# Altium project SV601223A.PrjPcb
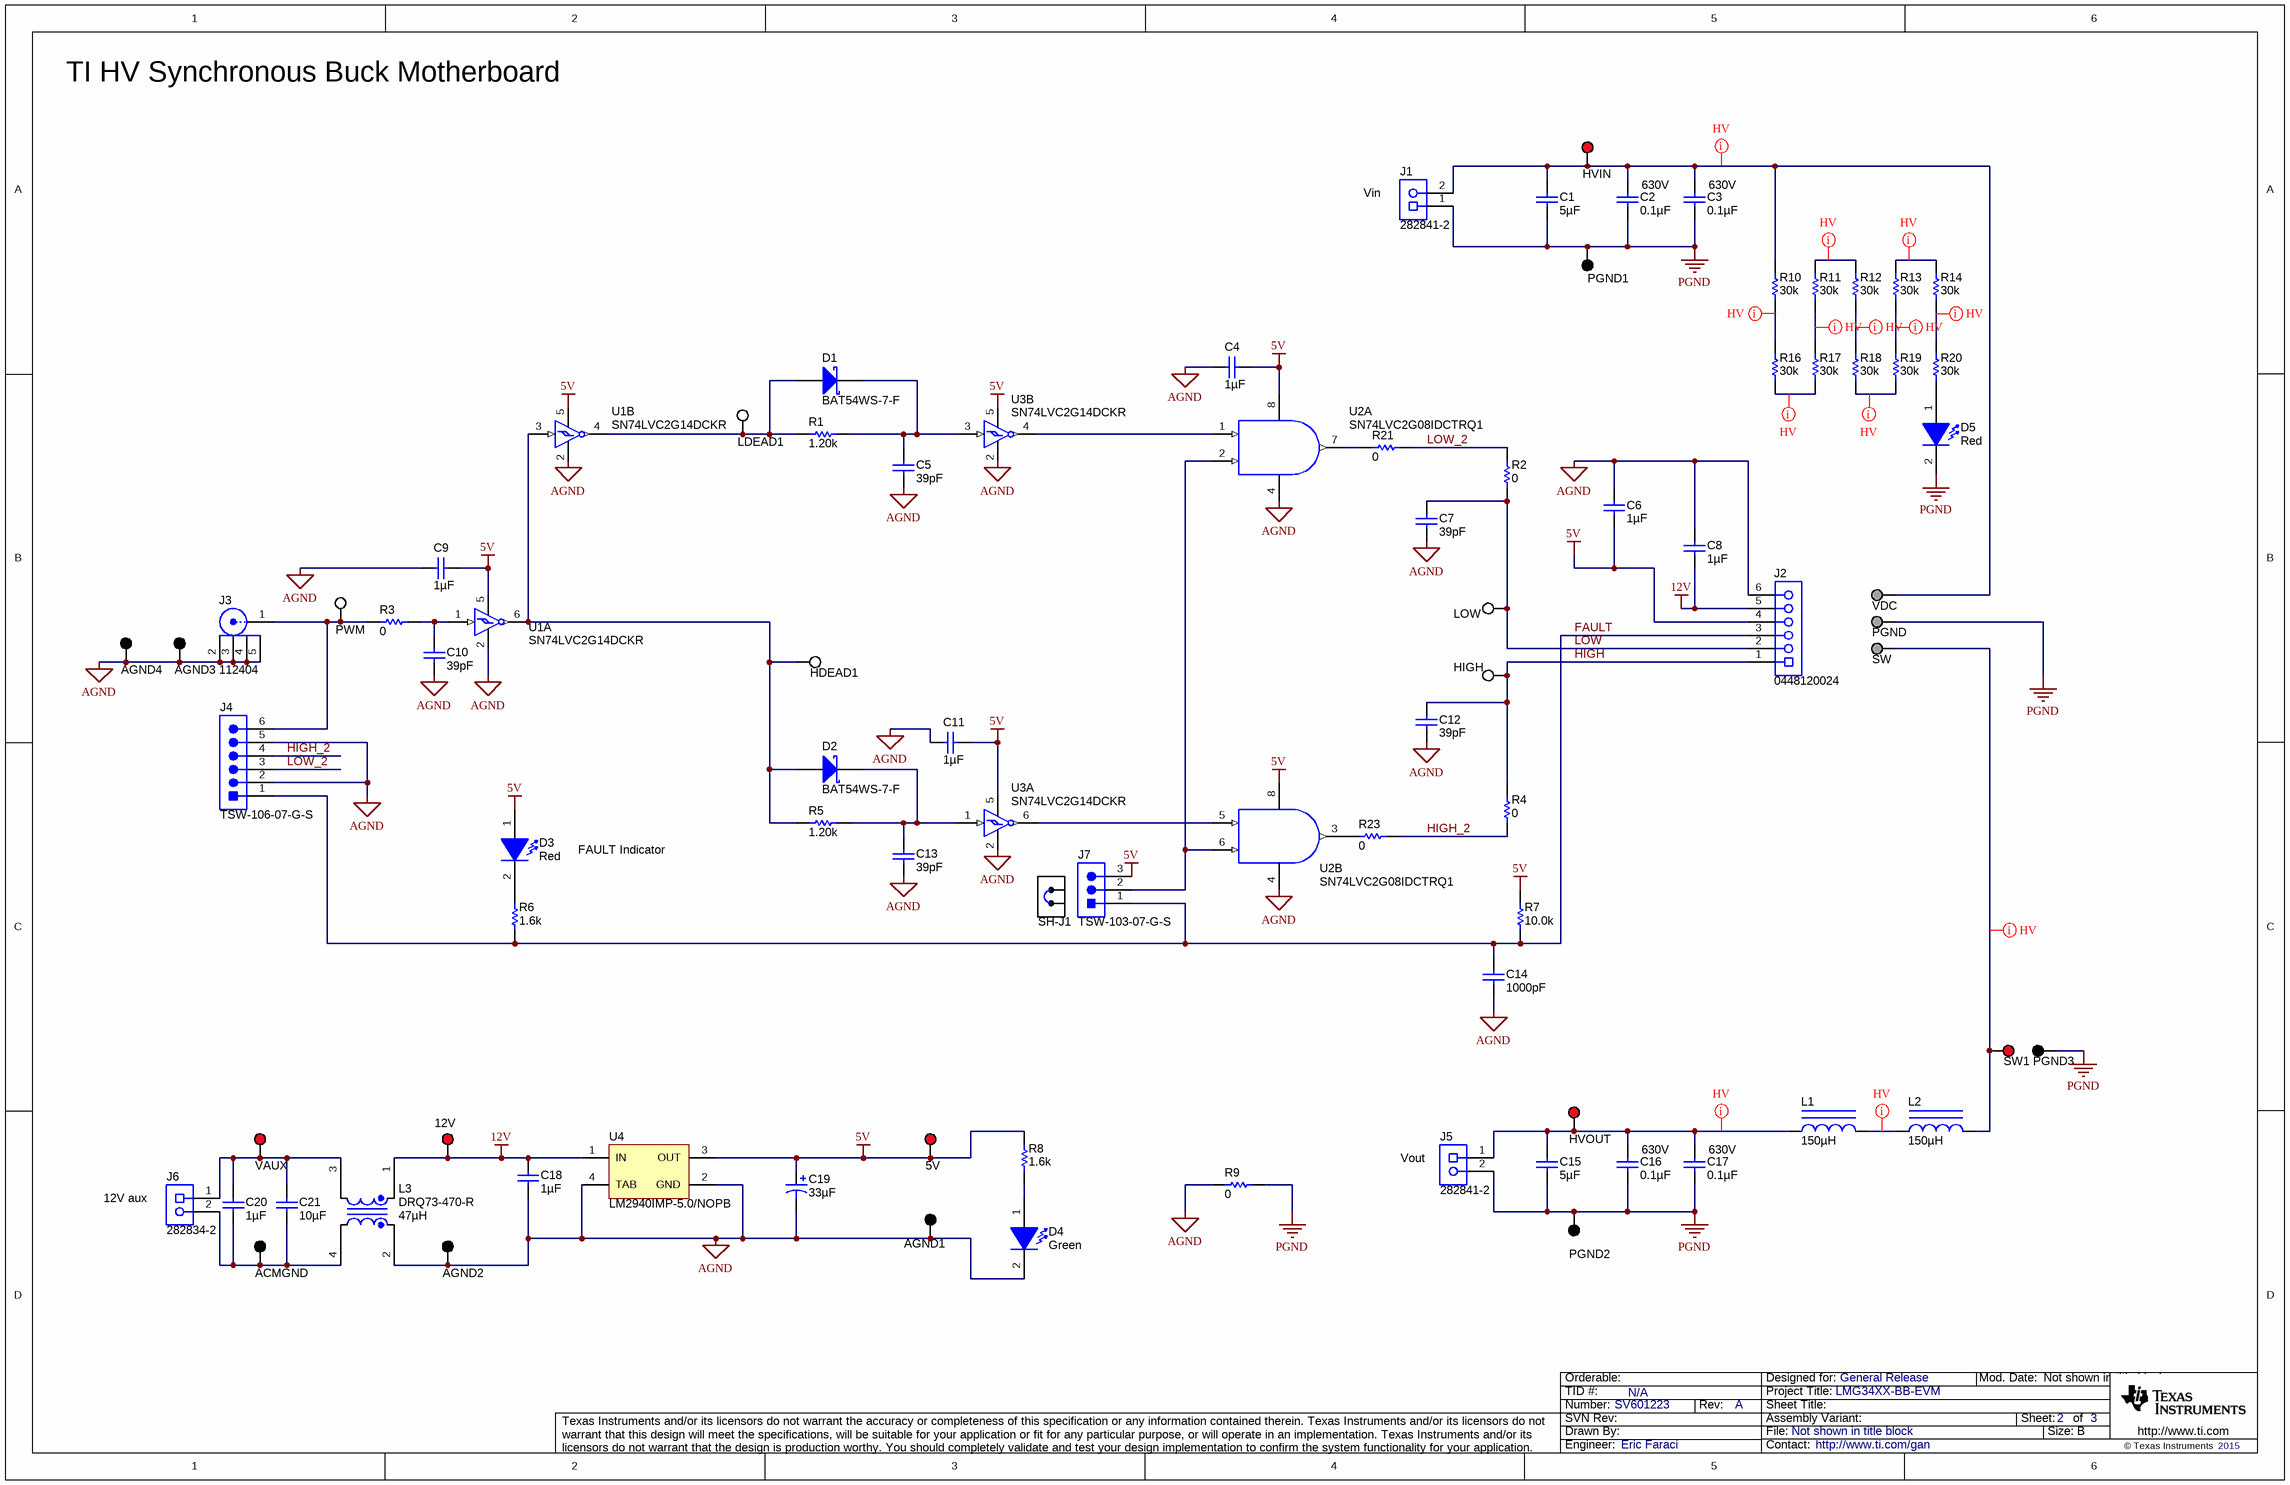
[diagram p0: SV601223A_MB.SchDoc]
TID: N/A; TechSupport: http://www.ti.com/gan; SCH_Rev: A; PRJ_Title: LMG34XX-BB-EVM; PRJ_Number: SV601223; PRJ_Engineer: Eric Faraci; PRJ_Customer: General Release; PCB_Rev: A; PCB_Layout: Eric Faraci; CopyrightYear: 2015
2 sheets, 112 parts. Net scope: global (net labels, ports and power ports of the same name join across sheets).
Board file: SV601223A.PcbDoc
Sheets:
  SV601223A_MB.SchDoc
  SV601223A_Hardware.SchDoc

## Sheet SV601223A_MB.SchDoc
size 431 x 279 mm; Date: Not shown in title block; ApprovedBy: Not shown in title block; CheckedBy: Not shown in title block; Author: Not shown in title block; CompanyName: Not shown in title block; Engineer: Not shown in title block; Organization: Not shown in title block; Address1: Not shown in title block; Address2: Not shown in title block; Address3: Not shown in title block; Address4: Not shown in title block; DocumentNumber: 1; Revision: Use project parameter SCH_Rev; SheetNumber: 2; SheetTotal: 3; PageSetup: Record=PageOptions¦CenterHorizontal=True¦CenterVertical=True¦PrintScale=1.00¦XCorrection=1.00¦YCorrection=1.00¦PrintKind=0¦BorderSize=5000000¦LeftOffset=0¦BottomOffset=0¦Orientation=2¦PaperLength=1000¦PaperWidth=1000¦Scale=100¦PaperSource=15¦PrintQuality=600¦MediaType=1¦DitherType=10¦PaperKind=Letter¦PrintScaleMode=1

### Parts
5V  5005  [Keystone5005]  (value not drawn)
12V  5005  [Keystone5005]  (value not drawn)
ACMGND  5006  [Keystone5006]  (value not drawn)
AGND1  5006  [Keystone5006]  (value not drawn)
AGND2  5006  [Keystone5006]  (value not drawn)
AGND3  5006  [Keystone5006]  (value not drawn)
AGND4  5006  [Keystone5006]  (value not drawn)
C1  ValueDisplayed: 5µF  [MKP1848Sx2_4200x1800x2700]  (hidden comment: MKP1848S55010JP2C)
C2  ValueDisplayed: 0.1µF  Value2: 630V  [1812]  (hidden comment: GRM43DR72J104KW01L)
C3  ValueDisplayed: 0.1µF  Value2: 630V  [1812]  (hidden comment: GRM43DR72J104KW01L)
C4  ValueDisplayed: 1µF  [0603]  (hidden comment: C1608X7R1E105K080AB)
C5  ValueDisplayed: 39pF  [0603]  (hidden comment: C1608C0G1H390J)
C6  ValueDisplayed: 1µF  [0603]  (hidden comment: C1608X7R1E105K080AB)
C7  ValueDisplayed: 39pF  [0603]  (hidden comment: C1608C0G1H390J)
C8  ValueDisplayed: 1µF  [0603]  (hidden comment: C1608X7R1E105K080AB)
C9  ValueDisplayed: 1µF  [0603]  (hidden comment: C1608X7R1E105K080AB)
C10  ValueDisplayed: 39pF  [0603]  (hidden comment: C1608C0G1H390J)
C11  ValueDisplayed: 1µF  [0603]  (hidden comment: C1608X7R1E105K080AB)
C12  ValueDisplayed: 39pF  [0603]  (hidden comment: C1608C0G1H390J)
C13  ValueDisplayed: 39pF  [0603]  (hidden comment: C1608C0G1H390J)
C14  ValueDisplayed: 1000pF  [0603]  (hidden comment: GRM1885C1E102JA01D)
C15  ValueDisplayed: 5µF  [MKP1848Sx2_4200x1800x2700]  (hidden comment: MKP1848S55010JP2C)
C16  ValueDisplayed: 0.1µF  Value2: 630V  [1812]  (hidden comment: GRM43DR72J104KW01L)
C17  ValueDisplayed: 0.1µF  Value2: 630V  [1812]  (hidden comment: GRM43DR72J104KW01L)
C18  ValueDisplayed: 1µF  [0603]  (hidden comment: GRM188R71E105KA12D)
C19  ValueDisplayed: 33µF  [3528-21]  (hidden comment: TPSB336K016R0350)
C20  ValueDisplayed: 1µF  [0603]  (hidden comment: GRM188R71E105KA12D)
C21  ValueDisplayed: 10µF  [0805_HV]  (hidden comment: GRM219R61E106KA12D)
D1  BAT54WS-7-F  [sod-323]
D2  BAT54WS-7-F  [sod-323]
D3  value Red  [LS L29K_Red]  (hidden comment: LS L29K-G1J2-1-Z)
D4  value Green  [LG L29K_GREEN]  (hidden comment: LG L29K-G2J1-24-Z)
D5  value Red  [LS L29K_Red]  (hidden comment: LS L29K-G1J2-1-Z)
HDEAD1  5012  [Keystone5012]  (value not drawn)
HIGH  5012  [Keystone5012]  (value not drawn)
HVIN  5005  [Keystone5005]  (value not drawn)
HVOUT  5005  [Keystone5005]  (value not drawn)
J1  282841-2  [TEC_282841-2]
J2  0448120024  [Molex_0448120024]
J3  112404  [Amphenol_112404]
J4  TSW-106-07-G-S  [TSW-106-07-G-S]
J5  282841-2  [TEC_282841-2]
J6  282834-2  [TEC_282834-2]
J7  TSW-103-07-G-S  [TSW-103-07-G-S]
L1  ValueDisplayed: 150µH  [2300HT-H]  (hidden comment: 2300HT-151-H-RC)
L2  ValueDisplayed: 150µH  [2300HT-H]  (hidden comment: 2300HT-151-H-RC)
L3  DRQ73-470-R  ValueDisplayed: 47µH  [DRQ73]
LDEAD1  5012  [Keystone5012]  (value not drawn)
LOW  5012  [Keystone5012]  (value not drawn)
PGND  Suggest using a net name here  [Mill-Max_0312-0-15-15-34-27-10-0]  (value not drawn)
PGND1  5006  [Keystone5006]  (value not drawn)
PGND2  5006  [Keystone5006]  (value not drawn)
PGND3  5006  [Keystone5006]  (value not drawn)
PWM  5012  [Keystone5012]  (value not drawn)
R1  ValueDisplayed: 1.20k  [0603]  (hidden comment: RC0603FR-071K2L)
R2  ValueDisplayed: 0  [0603]  (hidden comment: CRCW06030000Z0EA)
R3  ValueDisplayed: 0  [0603]  (hidden comment: CRCW06030000Z0EA)
R4  ValueDisplayed: 0  [0603]  (hidden comment: CRCW06030000Z0EA)
R5  ValueDisplayed: 1.20k  [0603]  (hidden comment: RC0603FR-071K2L)
R6  ValueDisplayed: 1.6k  [0603]  (hidden comment: CRCW06031K60JNEA)
R7  ValueDisplayed: 10.0k  [0603]  (hidden comment: ERJ-3EKF1002V)
R8  ValueDisplayed: 1.6k  [0603]  (hidden comment: CRCW06031K60JNEA)
R9  ValueDisplayed: 0  [0603]  (hidden comment: CRCW06030000Z0EA)
R10  ValueDisplayed: 30k  [1206]  (hidden comment: CRCW120630K0JNEA)
R11  ValueDisplayed: 30k  [1206]  (hidden comment: CRCW120630K0JNEA)
R12  ValueDisplayed: 30k  [1206]  (hidden comment: CRCW120630K0JNEA)
R13  ValueDisplayed: 30k  [1206]  (hidden comment: CRCW120630K0JNEA)
R14  ValueDisplayed: 30k  [1206]  (hidden comment: CRCW120630K0JNEA)
R16  ValueDisplayed: 30k  [1206]  (hidden comment: CRCW120630K0JNEA)
R17  ValueDisplayed: 30k  [1206]  (hidden comment: CRCW120630K0JNEA)
R18  ValueDisplayed: 30k  [1206]  (hidden comment: CRCW120630K0JNEA)
R19  ValueDisplayed: 30k  [1206]  (hidden comment: CRCW120630K0JNEA)
R20  ValueDisplayed: 30k  [1206]  (hidden comment: CRCW120630K0JNEA)
R21  ValueDisplayed: 0  [0603]  (hidden comment: CRCW06030000Z0EA)
R23  ValueDisplayed: 0  [0603]  (hidden comment: CRCW06030000Z0EA)
SH-J1  969102-0000-DA  [SNT-100-BK-G]  (value not drawn)
SW  Suggest using a net name here  [Mill-Max_0312-0-15-15-34-27-10-0]  (value not drawn)
SW1  5005  [Keystone5005]  (value not drawn)
U1  SN74LVC2G14DCKR  [DCK0006A_N]  (parts A,B of 2)
U2  SN74LVC2G08IDCTRQ1  [DCT0008A_N]  (parts A,B of 2)
U3  SN74LVC2G14DCKR  [DCK0006A_N]  (parts A,B of 2)
U4  LM2940IMP-5.0/NOPB  [MP04A_N]
VAUX  5005  [Keystone5005]  (value not drawn)
VDC  Suggest using a net name here  [Mill-Max_0312-0-15-15-34-27-10-0]  (value not drawn)

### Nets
5V: 5V.1 C4.2 C6.1 C9.2 C11.2 C19.1(+) D3.1(A) J2.4 J7.3 R7.2 R8.2 U1.5(VCC) U2.8(VCC) U3.5(VCC) U4.3(OUT)
12V: 12V.1 C8.1 C18.2 J2.5 L3.1 U4.1(IN)
AGND: AGND1.1 AGND2.1 AGND3.1 AGND4.1 C4.1 C5.2 C6.2 C7.2 C8.2 C9.1 C10.2 C11.1 C12.2 C13.2 C14.2 C18.1 C19.2(-) D4.2(K) J2.6 J3.2 J3.3 J3.4 J3.5 J4.2 J4.5 L3.2 R9.1 U1.2(GND) U2.4(GND) U3.2(GND) U4.2(GND) U4.4(TAB)
PGND: C1.2 C2.2 C3.2 C15.2 C16.2 C17.2 D5.2(K) J1.1 J5.2 PGND.1 PGND1.1 PGND2.1 PGND3.1 R9.2
FAULT: C14.1 J2.3 J4.1 J7.1 R6.1 R7.1
HIGH: C12.1 HIGH.1 J2.1 R4.2
HIGH_2: J4.4 R4.1 R23.1
LOW: C7.1 J2.2 LOW.1 R2.1
LOW_2: J4.3 R2.2 R21.1
NetACMGND_1: ACMGND.1 C20.1 C21.2 J6.2 L3.4
NetC1_1: C1.1 C2.1 C3.1 HVIN.1 J1.2 R10.2 VDC.1
NetC5_1: C5.1 D1.1(K) R1.2 U3.3(2A)
NetC10_1: C10.1 R3.1 U1.1(1A)
NetC13_1: C13.1 D2.1(K) R5.2 U3.1(1A)
NetC15_1: C15.1 C16.1 C17.1 HVOUT.1 J5.1 L1.1
NetC20_2: C20.2 C21.1 J6.1 L3.3 VAUX.1
NetD1_2: D1.2(A) LDEAD1.1 R1.1 U1.4(2Y)
NetD2_2: D2.2(A) HDEAD1.1 R5.1 U1.3(2A) U1.6(1Y)
NetD3_2: D3.2(K) R6.2
NetD4_1: D4.1(A) R8.1
NetD5_1: D5.1(A) R20.1
NetJ3_1: J3.1 J4.6 PWM.1 R3.2
NetJ7_2: J7.2 U2.2(1B) U2.6(2B)
NetL1_2: L1.2 L2.1
NetL2_2: L2.2 SW.1 SW1.1
NetR10_1: R10.1 R16.2
NetR11_1: R11.1 R17.2
NetR11_2: R11.2 R12.2
NetR12_1: R12.1 R18.2
NetR13_1: R13.1 R19.2
NetR13_2: R13.2 R14.2
NetR14_1: R14.1 R20.2
NetR16_1: R16.1 R17.1
NetR18_1: R18.1 R19.1
NetR21_2: R21.2 U2.7(1Y)
NetR23_2: R23.2 U2.3(2Y)
NetU2_1: U2.1(1A) U3.4(2Y)
NetU2_5: U2.5(2A) U3.6(1Y)

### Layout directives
net class HV: NetC1_1, NetC15_1, NetL1_2, NetL2_2, NetR10_1, NetR11_1, NetR11_2, NetR12_1, NetR13_1, NetR13_2, NetR14_1, NetR16_1, NetR18_1

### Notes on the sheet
- TI HV Synchronous Buck Motherboard
- (near J1) Vin
- FAULT Indicator
- (near J5) Vout
- (near J6) 12V aux

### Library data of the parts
5V 12V HVIN HVOUT SW1 VAUX = 5005: Test Point, Compact, Red, TH; Manufacturer: Keystone; CompType: Test Point Loop; U/M: EA
ACMGND AGND1-AGND4 PGND1-PGND3 = 5006: Test Point, Compact, Black, TH; Manufacturer: Keystone; CompType: Test Point Loop; U/M: EA
C1 C15 = MKP1848S55010JP2C: CAP, Film, 5 µF, 1000 V, +/- 5%, 0.016 ohm, TH; Manufacturer: Vishay-Bccomponents; Polarized: N; CompType: Capacitor; Value: 5uF; U/M: EA; Cap_F: 0.000005; Tolerance_%: 5; VDC_V: 1000; Value2: 1000V; ESR_ohm: 0.016; IRMS_A: 4.5; TaMin_C: -40; TaMax_C: 105; Cap_Case: 42x18x27mm
C2 C3 C16 C17 = GRM43DR72J104KW01L: CAP, CERM, 0.1uF, 630V, +/-10%, X7R, 1812; Manufacturer: MuRata; Polarized: N; CompType: Capacitor; U/M: EA; Cap_F: 0.0000001; Tolerance_%: 10; VDC_V: 630; TaMin_C: -55; TaMax_C: 125
C4 C6 C8 C9 C11 = C1608X7R1E105K080AB: CAP, CERM, 1 µF, 25 V, +/- 10%, X7R, 0603; Manufacturer: TDK; Polarized: N; CompType: Capacitor; Value: 1uF; U/M: EA; Cap_F: 0.000001; Tolerance_%: 10; Value1: Unknown; VDC_V: 25; Value2: 25V; TaMin_C: -55; TaMax_C: 125
C5 C7 C10 C12 C13 = C1608C0G1H390J: CAP, CERM, 39 pF, 50 V, +/- 5%, C0G/NP0, 0603; Manufacturer: TDK; Polarized: N; CompType: Capacitor; Value: 39pF; U/M: EA; Cap_F: 0.000000000039; Tolerance_%: 5; ESR_ohm: 0.2534; Value1: 0.2534 ohm; VDC_V: 50; Value2: 50V; TaMin_C: -55; TaMax_C: 125
C14 = GRM1885C1E102JA01D: CAP, CERM, 1000 pF, 25 V, +/- 5%, C0G/NP0, 0603; Manufacturer: MuRata; Polarized: N; CompType: Capacitor; Value: 1000pF; U/M: EA; Cap_F: 0.000000001; Tolerance_%: 5; Value1: Unknown; VDC_V: 25; Value2: 25V; TaMin_C: -55; TaMax_C: 125
C18 C20 = GRM188R71E105KA12D: CAP, CERM, 1 µF, 25 V, +/- 10%, X7R, 0603; Manufacturer: MuRata; Polarized: N; CompType: Capacitor; Value: 1uF; U/M: EA; Cap_F: 0.000001; Tolerance_%: 10; Value1: Unknown; VDC_V: 25; Value2: 25V; TaMin_C: -55; TaMax_C: 125
C19 = TPSB336K016R0350: CAP, TA, 33 µF, 16 V, +/- 10%, 0.35 ohm, SMD; Manufacturer: AVX; Polarized: Y; CompType: Capacitor; Value: 33uF; U/M: EA; Cap_F: 0.000033; Tolerance_%: 10; VDC_V: 16; Value2: 16V; ESR_ohm: 0.35; IRMS_A: 0.444; TaMin_C: -55; TaMax_C: 125; Cap_Case: B
C21 = GRM219R61E106KA12D: CAP, CERM, 10 µF, 25 V, +/- 10%, X5R, 0805; Manufacturer: MuRata; Polarized: N; CompType: Capacitor; Value: 10uF; U/M: EA; Cap_F: 0.00001; Tolerance_%: 10; Value1: Unknown; VDC_V: 25; Value2: 25V; TaMin_C: -55; TaMax_C: 85; Cap_Case: 0805
D1 D2 = BAT54WS-7-F: Diode, Schottky, 30 V, 0.2 A, SOD-323; Manufacturer: Diodes Inc.; U/M: EA; Vf_V: 0.7; Value: 30V; Value1: 0.2A; Value2: 0.7V; Io_A: 0.2; Vr_V: 30; TJmax_C: 125
D3 D5 = LS L29K-G1J2-1-Z: LED, Red, SMD; Manufacturer: OSRAM; Vf_V: 1.8; Value2: 1.8V; Io_A: 0.02; Vr_V: 12; Tjmax_C: 110; Value1: W; Angle: 160; U/M: EA
D4 = LG L29K-G2J1-24-Z: LED, Green, SMD; Manufacturer: OSRAM; Vf_V: 1.7; Value2: 1.7V; Io_A: 0.002; Tjmax_C: 110; Value1: W; U/M: EA
HDEAD1 HIGH LDEAD1 LOW PWM = 5012: Test Point, Multipurpose, White, TH; Manufacturer: Keystone; CompType: Test Point Loop; U/M: EA
J1 J5 = 282841-2: Terminal Block, 2x1, 5.08mm, TH; Manufacturer: TE Connectivity; SymbolCreator: a0412235; U/M: EA
J2 = 0448120024: Receptacle, 2.54mm, 6x1, Gold, TH; Manufacturer: Molex; SymbolCreator: a0411947; U/M: EA
J3 = 112404: Connector, TH, BNC; Manufacturer: Amphenol Connex; U/M: EA
J4 = TSW-106-07-G-S: Header, 100mil, 6x1, Gold, TH; Manufacturer: Samtec; SymbolCreator: a0412235; U/M: EA
J6 = 282834-2: Terminal Block, 2x1, 2.54mm, TH; Manufacturer: TE Connectivity; SymbolCreator: a0412235; U/M: EA
J7 = TSW-103-07-G-S: Header, 100mil, 3x1, Gold, TH; Manufacturer: Samtec; SymbolCreator: a0799628; U/M: EA
L1 L2 = 2300HT-151-H-RC: Inductor, Toroid, 150 µH, 7.5 A, 0.05 ohm, TH; Manufacturer: Bourns; Value: 150uH; Ind_H: 150.0E-6; Imax_A: 7.5; Irms: 7.5A @ 50C rise; DCR_ohm: 0.05; Value2: 7.5A; AEC Category: Q200; AEC Qualified: N
L3 = DRQ73-470-R: Coupled inductor, 47 µH, 1.14 A, 0.241 ohm, +/- 20%, SMD; Manufacturer: Cooper Bussman; SymbolCreator: a0412235; Ind_H: 47.0E-6; DCR_ohm: 0.241; Isat: 1.14; Tolerance_%: 20; Value: 47uH
PGND SW VDC = 0312-0-15-15-34-27-10-0: Pin Receptacle, .032-.046" .075" Dia, Gold, TH; Manufacturer: Mill-Max; U/M: EA
R1 R5 = RC0603FR-071K2L: RES, 1.20 k, 1%, 0.1 W, 0603; Manufacturer: Yageo America; CompType: Resistor; Value: 1.20k; Res_ohm: 1200; Value_Code: 1k20; Tolerance_%: 1; Power_W: 0.1; Value2: 0.1W; VDC_V: 150; TempCo: 200 ppm/C; U/M: EA
R2-R4 R9 R21 R23 = CRCW06030000Z0EA: RES, 0, 5%, 0.1 W, 0603; Manufacturer: Vishay-Dale; CompType: Resistor; Value: 0; Value_Code: 0000; Tolerance_%: 5; Power_W: 0.1; Value2: 0.1W; VDC_V: 75; TempCo: 200 ppm/C; EIA_Code: E24; U/M: EA
R6 R8 = CRCW06031K60JNEA: RES, 1.6 k, 5%, 0.1 W, 0603; Manufacturer: Vishay-Dale; CompType: Resistor; Value: 1.6k; Res_ohm: 1600; Value_Code: 1k60; Tolerance_%: 5; Power_W: 0.1; Value2: 0.1W; VDC_V: 75; TempCo: 200 ppm/C; EIA_Code: E24; U/M: EA
R7 = ERJ-3EKF1002V: RES, 10.0 k, 1%, 0.1 W, 0603; Manufacturer: Panasonic; CompType: Resistor; Value: 10.0k; Res_ohm: 10000; Value_Code: 10k0; Tolerance_%: 1; Power_W: 0.1; Value2: 0.1W; VDC_V: 75; TempCo: 100 ppm/C; EIA_Code: E96; U/M: EA
R10-R14 R16-R20 = CRCW120630K0JNEA: RES, 30 k, 5%, 0.25 W, 1206; Manufacturer: Vishay-Dale; CompType: Resistor; Value: 30k; Res_ohm: 30000; Value_Code: 30k0; Tolerance_%: 5; Power_W: 0.25; Value2: 0.25W; VDC_V: 200; TempCo: 200 ppm/C; EIA_Code: E24; U/M: EA
SH-J1 = 969102-0000-DA: Shunt, 100mil, Gold plated, Black; Manufacturer: 3M; Alternate Manufacturer: Samtec; Value: 1x2; Note: You can "mate" this to a header by matching the designator.  i.e. use SH-J3 for header J3
U1 U3 = SN74LVC2G14DCKR: Dual Schmitt-Trigger Inverter, DCK0006A; Alternate PartNumber: SN74LVC2G14DCKT; Manufacturer: Texas Instruments; SymbolCreator: a0411947; CompType: IC; U/M: EA
U2 = SN74LVC2G08IDCTRQ1: DUAL 2-INPUT POSITIVE-AND GATE, DCT0008A; Manufacturer: Texas Instruments; SymbolCreator: a0411947; CompType: IC; U/M: EA
U4 = LM2940IMP-5.0/NOPB: 1A Low Dropout Regulator, 4-pin SOT-223, Pb-Free; Manufacturer: Texas Instruments; PackageTopMarking: XYTT*L53B; PowerWise: N; CompType: LDO IC

## Sheet SV601223A_Hardware.SchDoc
size 431 x 279 mm; Date: Not shown in title block; ApprovedBy: Not shown in title block; CheckedBy: Not shown in title block; Author: Not shown in title block; CompanyName: Not shown in title block; Engineer: Not shown in title block; Organization: Not shown in title block; Address1: Not shown in title block; Address2: Not shown in title block; Address3: Not shown in title block; Address4: Not shown in title block; DocumentNumber: 1; Revision: Use project parameter SCH_Rev; SheetNumber: 3; SheetTotal: 3; PageSetup: Record=PageOptions¦CenterHorizontal=True¦CenterVertical=True¦PrintScale=1.00¦XCorrection=1.00¦YCorrection=1.00¦PrintKind=0¦BorderSize=5000000¦LeftOffset=0¦BottomOffset=0¦Orientation=2¦PaperLength=1000¦PaperWidth=1000¦Scale=100¦PaperSource=15¦PrintQuality=600¦MediaType=1¦DitherType=10¦PaperKind=Letter¦PrintScaleMode=1
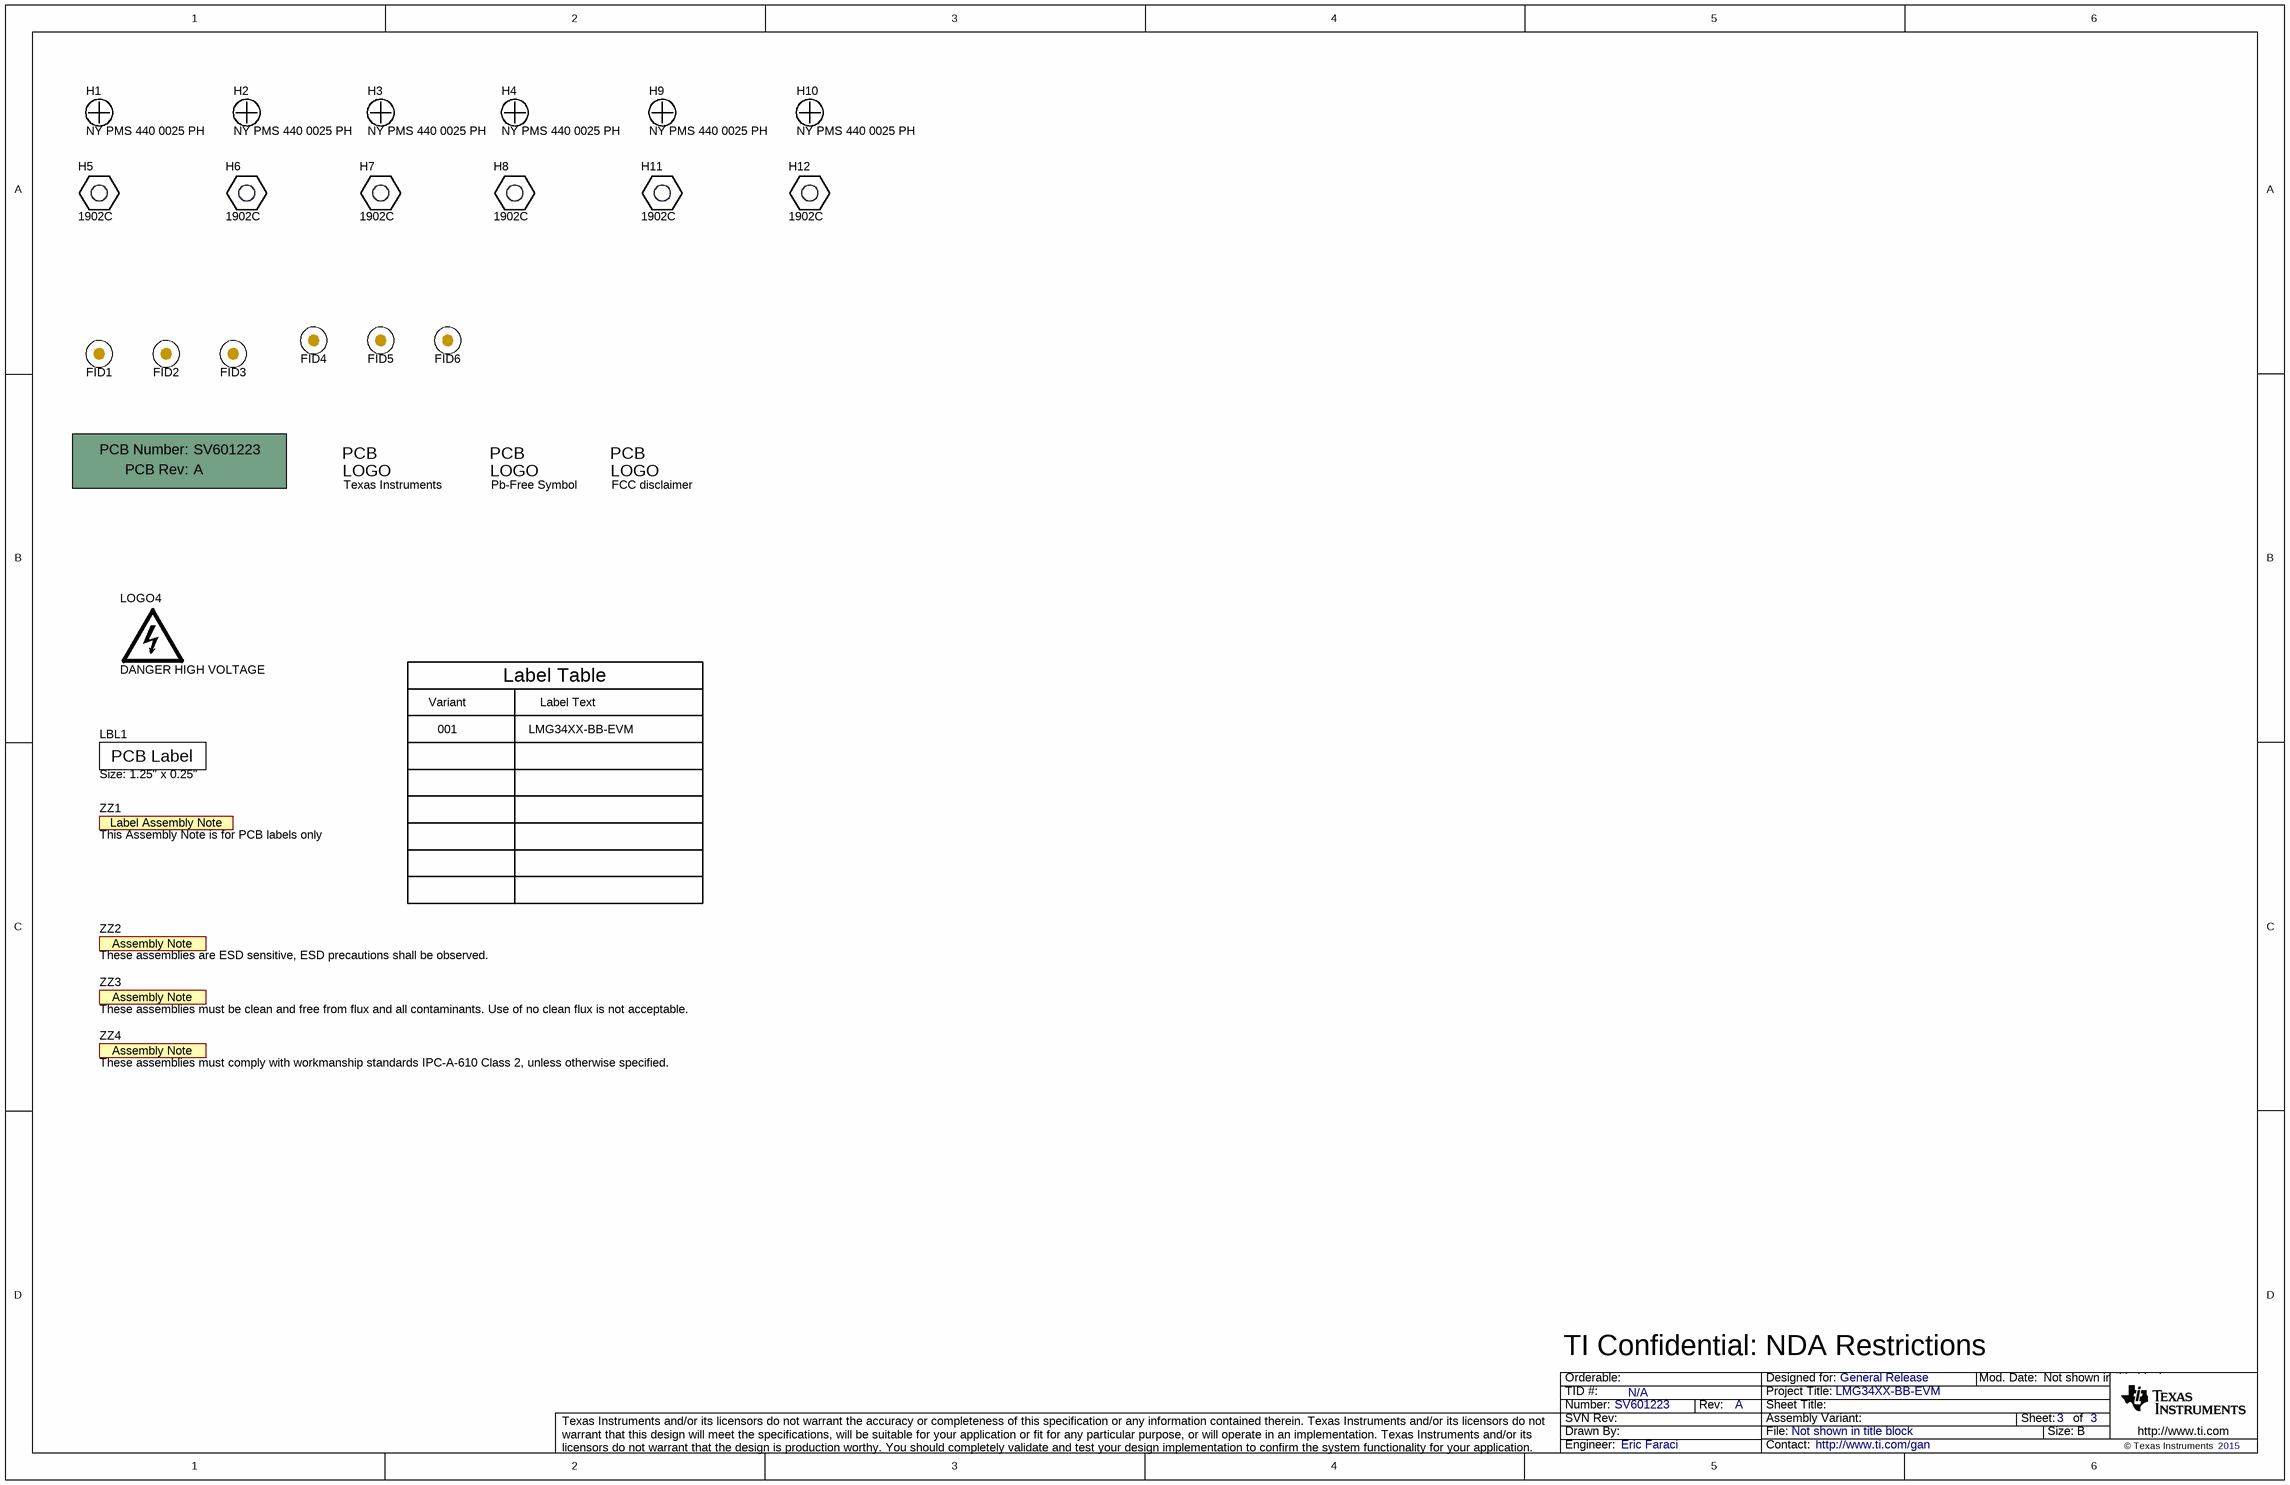
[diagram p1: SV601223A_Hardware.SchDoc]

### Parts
!PCB1  Printed Circuit Board  (value not drawn)  (mechanical)
FID1  Fiducial  [Fiducial10-20]  (value not drawn)
FID2  Fiducial  [Fiducial10-20]  (value not drawn)
FID3  Fiducial  [Fiducial10-20]  (value not drawn)
FID4  Fiducial  [Fiducial10-20]  (value not drawn)
FID5  Fiducial  [Fiducial10-20]  (value not drawn)
FID6  Fiducial  [Fiducial10-20]  (value not drawn)
H1  NY PMS 440 0025 PH  [NY PMS 440 0025 PH]
H2  NY PMS 440 0025 PH  [NY PMS 440 0025 PH]
H3  NY PMS 440 0025 PH  [NY PMS 440 0025 PH]
H4  NY PMS 440 0025 PH  [NY PMS 440 0025 PH]
H5  1902C  [Keystone_1902C]
H6  1902C  [Keystone_1902C]
H7  1902C  [Keystone_1902C]
H8  1902C  [Keystone_1902C]
H9  NY PMS 440 0025 PH  [NY PMS 440 0025 PH]
H10  NY PMS 440 0025 PH  [NY PMS 440 0025 PH]
H11  1902C  [Keystone_1902C]
H12  1902C  [Keystone_1902C]
LBL1  Size: 1.25" x 0.25"  [Label_1250x250]
Logo1  Texas Instruments  [TI_Stacked_SolderMask_Medium]  (no BOM)
Logo2  Pb-Free Symbol  [Pb-Free_Overlay_Small]  (no BOM)
Logo3  FCC disclaimer  [FCC_disclaimer_stacked]  (no BOM)
LOGO4  DANGER HIGH VOLTAGE  [IEC_HighVoltage_Medium]  (no BOM)
ZZ1  This Assembly Note is for PCB labels only  [AssemblyNoteLabel]  (no BOM)
ZZ2  These assemblies are ESD sensitive, ESD precautions shall be observed.  [AssemblyNote]  (no BOM)
ZZ3  These assemblies must be clean and free from flux and all contaminants. Use of no clean flux is not acceptable.  [AssemblyNote]  (no BOM)
ZZ4  These assemblies must comply with workmanship standards IPC-A-610 Class 2, unless otherwise specified.  [AssemblyNote]  (no BOM)

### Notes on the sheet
- Variant
- Label Table
- Label Text
- 001
- LMG34XX-BB-EVM
- TI Confidential: NDA Restrictions

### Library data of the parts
!PCB1 = PCB: Manufacturer: Any; PartNumber: SV601223; SymbolCreator: a0412235
FID1-FID6 = Fiducial: Fiducial mark.  There is nothing to buy or mount.; SymbolCreator: codlsc
H1-H4 H9 H10 = NY PMS 440 0025 PH: Machine Screw, Round, #4-40 x 1/4, Nylon, Philips panhead; Manufacturer: B&F Fastener Supply; CompType: Hardware; SymbolCreator: codlsc; U/M: EA
H5-H8 H11 H12 = 1902C: Standoff, Hex, 0.5"L #4-40 Nylon; Manufacturer: Keystone; CompType: Hardware
LBL1 = THT-13-457-10: Thermal Transfer Printable Labels, 1.250" W x 0.250" H - 10,000 per roll; Manufacturer: Brady; SymbolCreator: a0412235; CompType: Label
Logo1 = TI_Logo: Texas Instrument Corporate Signature; SymbolCreator: codlsc
Logo2 = Pb-Free: SymbolCreator: a0412235
Logo3 = FCC_disclaimer: SymbolCreator: codlsc
LOGO4 = IEC_HighVoltage: IEC 61010-1 High Voltage Warning; SymbolCreator: a0412235
ZZ1 = AssemblyNoteLabel: SymbolCreator: a0412235
ZZ2-ZZ4 = AssemblyNote: SymbolCreator: codlsc

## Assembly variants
001: not fitted AGND3 AGND4 C10 C12 C? FID1 FID2 FID3 HDEAD1 HIGH LDEAD1 LOW PGND3 PWM SW1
